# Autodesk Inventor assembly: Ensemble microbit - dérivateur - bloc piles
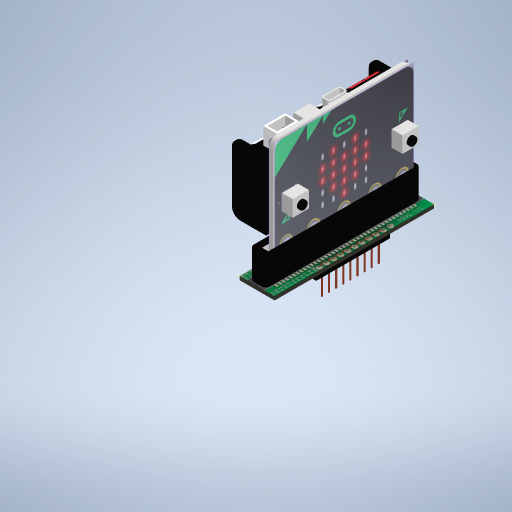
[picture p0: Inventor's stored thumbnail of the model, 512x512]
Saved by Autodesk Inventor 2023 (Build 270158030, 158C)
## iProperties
Created: 2022-12
Part Number: Ensemble microbit - dérivateur - bloc piles
Document SubType Name: Assembly
Designer: ecuenot
Author: ecuenot
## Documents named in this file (4)
- D:\boitier\Ensemble microbit - dérivateur - bloc piles.iam
- D:\boitier\microbit.ipt
- D:\boitier\Dérivation Kitronik.ipt
- D:\boitier\boitier-piles-2.ipt
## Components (3 placed, 3 different names)
1. microbit:1 — Placage:1, Placage:2, Affleurement:1, Placage:3, Placage:4, Placage:5
2. Dérivation Kitronik:1 — Placage:3, Placage:4, Placage:5
3. boitier-piles-2:1 — Placage:1, Placage:2, Affleurement:1
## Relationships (6: Mate 5, Flush 1)
- Placage:1 [Mate]: microbit:1 ↔ boitier-piles-2:1
- Placage:2 [Mate]: microbit:1 ↔ boitier-piles-2:1
- Affleurement:1 [Flush]: microbit:1 ↔ boitier-piles-2:1
- Placage:3 [Mate]: microbit:1 ↔ Dérivation Kitronik:1
- Placage:4 [Mate]: microbit:1 ↔ Dérivation Kitronik:1
- Placage:5 [Mate]: microbit:1 ↔ Dérivation Kitronik:1
